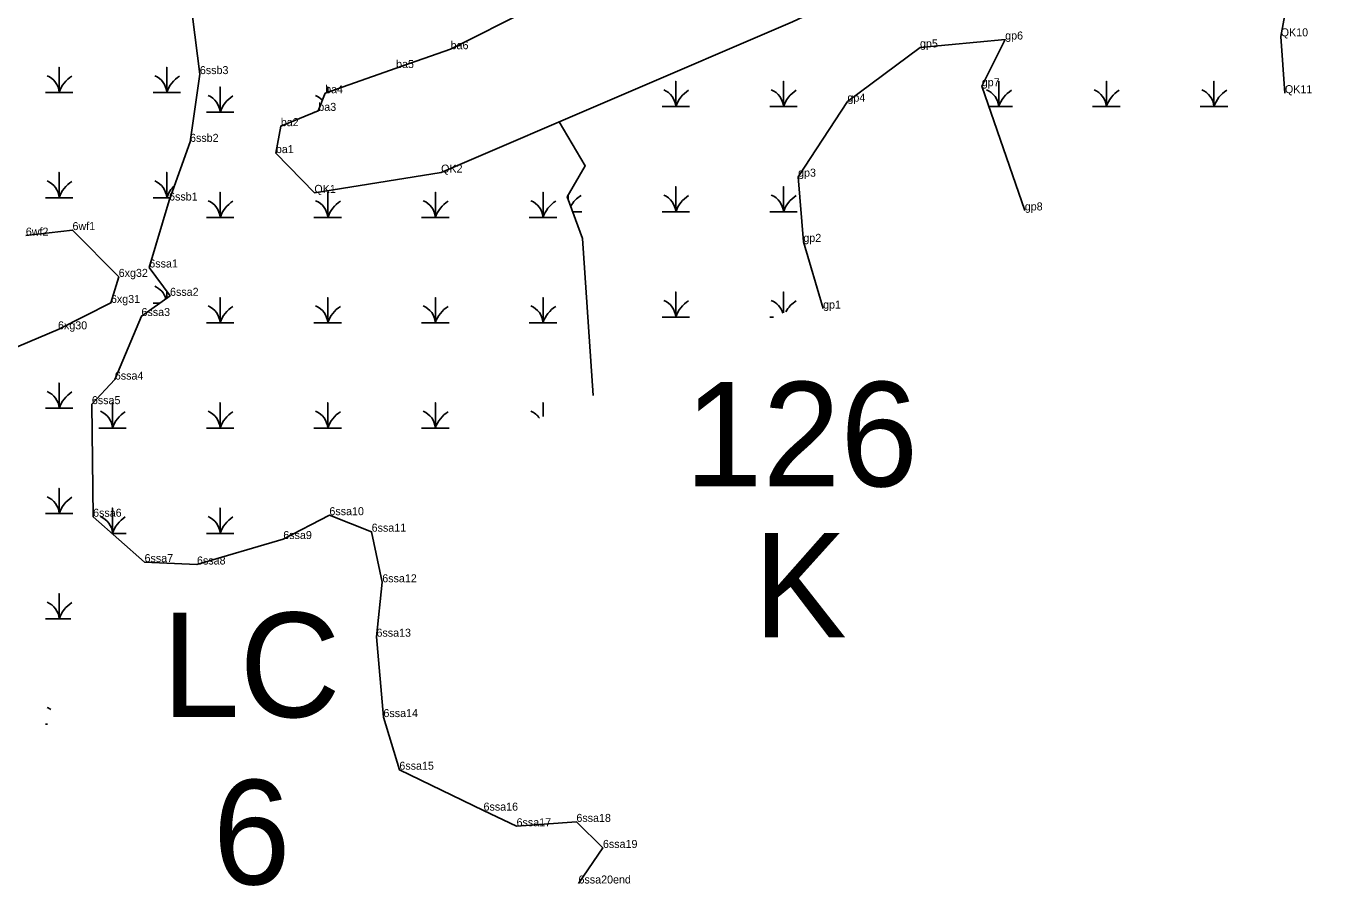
# Model space of a CAD drawing. Extents: x 2072529 to 2268796, y 436423 to 470397.
# Drawn here: x 2153347 to 2154163, y 438196 to 438734 of the extents above; entities that cross this region are included whole.
import ezdxf

# ---------------------------------------------------------------- set-up
doc = ezdxf.new("R2010")
doc.units = 0
for name, color, linetype in [('Default', 7, 'Continuous'), ('Exist Environmental Wetland Boundary', 7, 'Continuous'), ('Exist Environmental Wetland Boundary Cogo Comment', 7, 'Continuous'), ('Exist Environmental Wetland Boundary Cogo Point CELL', 7, 'Continuous'), ('Exist Hydro Jurisdictional Stream or Body of Water NEU Mitigable', 7, 'Continuous'), ('Exist Hydro Jurisdictional Stream or Body of Water NEU Mitigable Cogo Comment', 7, 'Continuous'), ('Exist Hydro Swamp or Marsh', 7, 'Continuous')]:
    doc.layers.add(name, color=color, linetype=linetype)

msp = doc.modelspace()

# ---------------------------------------------------------------- linework, layer by layer
at = {"layer": 'Exist Environmental Wetland Boundary'}
for points in [[(2153527.37, 438629.46), (2153503.31, 438654.33), (2153506.4, 438671.17), (2153529.85, 438680.72), (2153534.13, 438691.75), (2153578.44, 438707.49), (2153612.52, 438719.25), (2153662.11, 438744.35), (2153706.16, 438766.61), (2153742.6, 438780.8), (2153776.72, 438794.85), (2153822.89, 438806.64), (2153857.62, 438820.19), (2153907.12, 438843.71), (2153953.02, 438868.13), (2154021.3, 438890.53), (2154083.94, 438920.93), (2154164.03, 438955.62)], [(2153527.37, 438629.46), (2153606.57, 438642.14), (2153826.22, 438736.39), (2153937.5, 438788.93), (2154046.6, 438844.6), (2154149.14, 438888.4), (2154150.77, 438865.09), (2154136.41, 438848.89), (2154143.66, 438795.63), (2154131.16, 438727.3), (2154133.8, 438691.78)], [(2153845.24, 438557.14), (2153832.91, 438598.85), (2153829.61, 438639.59), (2153860.44, 438686.49), (2153905.78, 438720.37), (2153959, 438725.3), (2153944.36, 438696.13), (2153971.25, 438618.48)], [(2153680.4, 438673.82), (2153696.61, 438646.37), (2153685.41, 438626.93), (2153694.89, 438601), (2153701.53, 438502.86)], [(2153347.1, 438602.75), (2153376.26, 438606.21), (2153405.12, 438576.96), (2153400.27, 438560.67), (2153367.2, 438544.18), (2153242.69, 438491.33)]]:
    msp.add_lwpolyline(points, dxfattribs=at)
at = {"layer": 'Exist Environmental Wetland Boundary Cogo Point CELL'}
for p, q in [((2154131.16, 438727.3), (2154131.16, 438727.3)), ((2153612.52, 438719.25), (2153612.52, 438719.25)), ((2153905.78, 438720.37), (2153905.78, 438720.37)), ((2153959, 438725.3), (2153959, 438725.3)), ((2153455.83, 438703.7), (2153455.83, 438703.7)), ((2153578.44, 438707.49), (2153578.44, 438707.49)), ((2153944.36, 438696.13), (2153944.36, 438696.13)), ((2153534.13, 438691.75), (2153534.13, 438691.75)), ((2153860.44, 438686.49), (2153860.44, 438686.49)), ((2154133.8, 438691.78), (2154133.8, 438691.78)), ((2153529.85, 438680.72), (2153529.85, 438680.72)), ((2153506.4, 438671.17), (2153506.4, 438671.17)), ((2153449.69, 438661.35), (2153449.69, 438661.35)), ((2153503.31, 438654.33), (2153503.31, 438654.33)), ((2153606.57, 438642.14), (2153606.57, 438642.14)), ((2153829.61, 438639.59), (2153829.61, 438639.59)), ((2153527.37, 438629.46), (2153527.37, 438629.46)), ((2153436.6, 438624.69), (2153436.6, 438624.69)), ((2153971.25, 438618.48), (2153971.25, 438618.48)), ((2153376.26, 438606.21), (2153376.26, 438606.21)), ((2153376.26, 438606.21), (2153376.26, 438606.21)), ((2153832.91, 438598.85), (2153832.91, 438598.85)), ((2153424.24, 438582.83), (2153424.24, 438582.83)), ((2153405.12, 438576.96), (2153405.12, 438576.96)), ((2153405.12, 438576.96), (2153405.12, 438576.96)), ((2153437.19, 438565.13), (2153437.19, 438565.13)), ((2153400.27, 438560.67), (2153400.27, 438560.67)), ((2153400.27, 438560.67), (2153400.27, 438560.67)), ((2153845.24, 438557.14), (2153845.24, 438557.14)), ((2153419.35, 438552.51), (2153419.35, 438552.51)), ((2153367.2, 438544.18), (2153367.2, 438544.18)), ((2153367.2, 438544.18), (2153367.2, 438544.18)), ((2153402.71, 438512.76), (2153402.71, 438512.76)), ((2153388.36, 438497.43), (2153388.36, 438497.43)), ((2153389.11, 438427.05), (2153389.11, 438427.05)), ((2153536.77, 438428.03), (2153536.77, 438428.03)), ((2153563.17, 438417.71), (2153563.17, 438417.71)), ((2153507.95, 438413.11), (2153507.95, 438413.11)), ((2153421.28, 438398.69), (2153421.28, 438398.69)), ((2153454.04, 438397.21), (2153454.04, 438397.21)), ((2153569.81, 438386.09), (2153569.81, 438386.09)), ((2153566.18, 438352.08), (2153566.18, 438352.08)), ((2153570.53, 438301.85), (2153570.53, 438301.85)), ((2153580.48, 438268.96), (2153580.48, 438268.96)), ((2153633.07, 438243.38), (2153633.07, 438243.38)), ((2153653.71, 438233.61), (2153653.71, 438233.61)), ((2153691.09, 438236.34), (2153691.09, 438236.34)), ((2153707.68, 438220.06), (2153707.68, 438220.06)), ((2153692.42, 438197.84), (2153692.42, 438197.84))]:
    msp.add_line(p, q, dxfattribs=at)
at = {"layer": 'Exist Hydro Jurisdictional Stream or Body of Water NEU Mitigable'}
for points in [[(2153424.24, 438582.83), (2153436.6, 438624.69), (2153449.69, 438661.35), (2153455.83, 438703.7), (2153451.31, 438739.61), (2153439.32, 438771.61), (2153434.48, 438810.6), (2153429.14, 438886.46), (2153428.13, 438953.78), (2153424.11, 438991.65), (2153418.44, 439064.82)], [(2153692.42, 438197.84), (2153707.68, 438220.06), (2153691.09, 438236.34), (2153653.71, 438233.61), (2153633.07, 438243.38), (2153580.48, 438268.96), (2153570.53, 438301.85), (2153566.18, 438352.08), (2153569.81, 438386.09), (2153563.17, 438417.71), (2153536.77, 438428.03), (2153507.95, 438413.11), (2153454.04, 438397.21), (2153421.28, 438398.69), (2153389.11, 438427.05), (2153388.36, 438497.43), (2153402.71, 438512.76), (2153419.35, 438552.51), (2153437.19, 438565.13), (2153424.24, 438582.83)]]:
    msp.add_lwpolyline(points, dxfattribs=at)
at = {"layer": 'Exist Hydro Swamp or Marsh'}
for points in [[(2153359.31, 438692.23), (2153367.91, 438692.23), (2153367.91, 438708.01), (2153367.91, 438692.23), (2153376.51, 438692.23)], [(2153426.56, 438692.23), (2153435.16, 438692.23), (2153435.16, 438708.01), (2153435.16, 438692.23), (2153443.76, 438692.23)], [(2153459.88, 438679.88), (2153468.48, 438679.88), (2153468.48, 438695.66), (2153468.48, 438679.88), (2153477.08, 438679.88)], [(2153535.73, 438692.32), (2153535.73, 438695.66), (2153535.73, 438692.32)], [(2153744.61, 438683.41), (2153753.21, 438683.41), (2153753.21, 438699.19), (2153753.21, 438683.41), (2153761.81, 438683.41)], [(2153811.86, 438683.41), (2153820.46, 438683.41), (2153820.46, 438699.19), (2153820.46, 438683.41), (2153829.06, 438683.41)], [(2153948.77, 438683.41), (2153954.96, 438683.41), (2153954.96, 438699.19), (2153954.96, 438683.41), (2153963.56, 438683.41)], [(2154013.61, 438683.41), (2154022.21, 438683.41), (2154022.21, 438699.19), (2154022.21, 438683.41), (2154030.81, 438683.41)], [(2154080.86, 438683.41), (2154089.46, 438683.41), (2154089.46, 438699.19), (2154089.46, 438683.41), (2154098.06, 438683.41)], [(2153527.13, 438679.88), (2153527.8, 438679.88)], [(2153359.31, 438626.43), (2153367.91, 438626.43), (2153367.91, 438642.21), (2153367.91, 438626.43), (2153376.51, 438626.43)], [(2153426.56, 438626.43), (2153435.16, 438626.43), (2153435.16, 438642.21), (2153435.16, 438626.43), (2153437.22, 438626.43)], [(2153459.88, 438614.08), (2153468.48, 438614.08), (2153468.48, 438629.86), (2153468.48, 438614.08), (2153477.08, 438614.08)], [(2153527.13, 438614.08), (2153535.73, 438614.08), (2153535.73, 438629.86), (2153535.73, 438614.08), (2153544.33, 438614.08)], [(2153594.38, 438614.08), (2153602.98, 438614.08), (2153602.98, 438629.86), (2153602.98, 438614.08), (2153611.58, 438614.08)], [(2153661.63, 438614.08), (2153670.23, 438614.08), (2153670.23, 438629.86), (2153670.23, 438614.08), (2153678.83, 438614.08)], [(2153744.61, 438617.61), (2153753.21, 438617.61), (2153753.21, 438633.39), (2153753.21, 438617.61), (2153761.81, 438617.61)], [(2153811.86, 438617.61), (2153820.46, 438617.61), (2153820.46, 438633.39), (2153820.46, 438617.61), (2153829.06, 438617.61)], [(2153685.96, 438625.43), (2153685.96, 438627.88)], [(2153685.96, 438627.88), (2153685.96, 438625.43)], [(2153688.82, 438617.61), (2153694.56, 438617.61)], [(2153435.16, 438563.7), (2153435.16, 438567.9)], [(2153435.16, 438567.9), (2153435.16, 438563.7)], [(2153459.88, 438548.28), (2153468.48, 438548.28), (2153468.48, 438564.06), (2153468.48, 438548.28), (2153477.08, 438548.28)], [(2153527.13, 438548.28), (2153535.73, 438548.28), (2153535.73, 438564.06), (2153535.73, 438548.28), (2153544.33, 438548.28)], [(2153594.38, 438548.28), (2153602.98, 438548.28), (2153602.98, 438564.06), (2153602.98, 438548.28), (2153611.58, 438548.28)], [(2153661.63, 438548.28), (2153670.23, 438548.28), (2153670.23, 438564.06), (2153670.23, 438548.28), (2153678.83, 438548.28)], [(2153744.61, 438551.81), (2153753.21, 438551.81), (2153753.21, 438567.59), (2153753.21, 438551.81), (2153761.81, 438551.81)], [(2153820.46, 438554.47), (2153820.46, 438567.59), (2153820.46, 438554.47)], [(2153426.56, 438560.63), (2153430.82, 438560.63)], [(2153811.86, 438551.81), (2153814.34, 438551.81)], [(2153359.31, 438494.83), (2153367.91, 438494.83), (2153367.91, 438510.61), (2153367.91, 438494.83), (2153376.51, 438494.83)], [(2153392.63, 438482.48), (2153401.23, 438482.48), (2153401.23, 438498.26), (2153401.23, 438482.48), (2153409.83, 438482.48)], [(2153459.88, 438482.48), (2153468.48, 438482.48), (2153468.48, 438498.26), (2153468.48, 438482.48), (2153477.08, 438482.48)], [(2153527.13, 438482.48), (2153535.73, 438482.48), (2153535.73, 438498.26), (2153535.73, 438482.48), (2153544.33, 438482.48)], [(2153594.38, 438482.48), (2153602.98, 438482.48), (2153602.98, 438498.26), (2153602.98, 438482.48), (2153611.58, 438482.48)], [(2153670.23, 438489.62), (2153670.23, 438498.26), (2153670.23, 438489.62)], [(2153359.31, 438429.03), (2153367.91, 438429.03), (2153367.91, 438444.81), (2153367.91, 438429.03), (2153376.51, 438429.03)], [(2153400.87, 438416.68), (2153401.23, 438416.68), (2153401.23, 438432.46), (2153401.23, 438416.68), (2153409.83, 438416.68)], [(2153459.88, 438416.68), (2153468.48, 438416.68), (2153468.48, 438432.46), (2153468.48, 438416.68), (2153477.08, 438416.68)], [(2153359.31, 438363.23), (2153367.91, 438363.23), (2153367.91, 438379.01), (2153367.91, 438363.23), (2153375.22, 438363.23)], [(2153359.31, 438297.43), (2153360.73, 438297.43)]]:
    msp.add_lwpolyline(points, dxfattribs=at)
for centre, radius, start, end in [((2153355.65, 438691.34), 12.3, 4.14034, 67.53497), ((2153386.15, 438686.16), 19.22, 122.12745, 161.62219), ((2153422.9, 438691.34), 12.3, 4.14034, 67.53497), ((2153453.4, 438686.16), 19.22, 122.12745, 161.62219), ((2153740.94, 438682.52), 12.3, 4.14034, 67.53497), ((2153771.45, 438677.35), 19.22, 122.12745, 161.62219), ((2153808.19, 438682.52), 12.3, 4.14034, 67.53497), ((2153838.7, 438677.35), 19.22, 122.12745, 161.62219), ((2153942.69, 438682.52), 12.3, 4.14034, 67.53497), ((2153973.2, 438677.35), 19.22, 122.12745, 161.62219), ((2154009.94, 438682.52), 12.3, 4.14034, 67.53497), ((2154040.45, 438677.35), 19.22, 122.12745, 161.62219), ((2154077.19, 438682.52), 12.3, 4.14034, 67.53497), ((2154107.7, 438677.35), 19.22, 122.12745, 161.62219), ((2153456.22, 438679), 12.3, 4.14034, 67.53497), ((2153486.72, 438673.82), 19.22, 122.12745, 161.62219), ((2153523.47, 438679), 12.3, 43.10712, 67.53497), ((2153355.65, 438625.54), 12.3, 4.14034, 67.53497), ((2153386.15, 438620.36), 19.22, 122.12745, 161.62219), ((2153422.9, 438625.54), 12.3, 4.14034, 67.53497), ((2153453.4, 438620.36), 19.22, 134.35762, 161.62219), ((2153740.94, 438616.72), 12.3, 4.14034, 67.53497), ((2153808.19, 438616.72), 12.3, 4.14034, 67.53497), ((2153456.22, 438613.2), 12.3, 4.14034, 67.53497), ((2153486.72, 438608.02), 19.22, 122.12745, 161.62219), ((2153523.47, 438613.2), 12.3, 4.14034, 67.53497), ((2153553.97, 438608.02), 19.22, 122.12745, 161.62219), ((2153590.72, 438613.2), 12.3, 4.14034, 67.53497), ((2153621.22, 438608.02), 19.22, 122.12745, 161.62219), ((2153657.97, 438613.2), 12.3, 4.14034, 67.53497), ((2153688.47, 438608.02), 19.22, 122.12745, 161.62219), ((2153704.2, 438611.55), 19.22, 122.12745, 150.1359), ((2153771.45, 438611.55), 19.22, 122.12745, 161.62219), ((2153838.7, 438611.55), 19.22, 122.12745, 161.62219), ((2153422.9, 438559.74), 12.3, 17.0299, 67.53497), ((2153456.22, 438547.4), 12.3, 4.14034, 67.53497), ((2153486.72, 438542.22), 19.22, 122.12745, 161.62219), ((2153523.47, 438547.4), 12.3, 4.14034, 67.53497), ((2153553.97, 438542.22), 19.22, 122.12745, 161.62219), ((2153590.72, 438547.4), 12.3, 4.14034, 67.53497), ((2153621.22, 438542.22), 19.22, 122.12745, 161.62219), ((2153657.97, 438547.4), 12.3, 4.14034, 67.53497), ((2153688.47, 438542.22), 19.22, 122.12745, 161.62219), ((2153740.94, 438550.92), 12.3, 4.14034, 67.53497), ((2153771.45, 438545.75), 19.22, 122.12745, 161.62219), ((2153808.19, 438550.92), 12.3, 15.83458, 67.53497), ((2153838.7, 438545.75), 19.22, 122.12745, 150.91872), ((2153355.65, 438493.94), 12.3, 4.14034, 67.53497), ((2153386.15, 438488.76), 19.22, 122.12745, 161.62219), ((2153388.97, 438481.6), 12.3, 4.14034, 67.53497), ((2153419.47, 438476.42), 19.22, 122.12745, 161.62219), ((2153456.22, 438481.6), 12.3, 4.14034, 67.53497), ((2153486.72, 438476.42), 19.22, 122.12745, 161.62219), ((2153523.47, 438481.6), 12.3, 4.14034, 67.53497), ((2153553.97, 438476.42), 19.22, 122.12745, 161.62219), ((2153590.72, 438481.6), 12.3, 4.14034, 67.53497), ((2153621.22, 438476.42), 19.22, 122.12745, 161.62219), ((2153657.97, 438481.6), 12.3, 35.17036, 67.53497), ((2153355.65, 438428.14), 12.3, 4.14034, 67.53497), ((2153386.15, 438422.96), 19.22, 122.12745, 161.62219), ((2153388.97, 438415.8), 12.3, 4.14034, 67.53497), ((2153419.47, 438410.62), 19.22, 122.12745, 161.62219), ((2153456.22, 438415.8), 12.3, 4.14034, 67.53497), ((2153486.72, 438410.62), 19.22, 122.12745, 161.62219), ((2153355.65, 438362.34), 12.3, 4.14034, 67.53497), ((2153386.15, 438357.16), 19.22, 122.12745, 161.62219), ((2153355.65, 438296.54), 12.3, 54.72067, 67.53497)]:
    msp.add_arc(centre, radius, start, end, dxfattribs=at)

# ---------------------------------------------------------------- texts
at = {"layer": 'Default'}
for s, p in [('126', (2153758.8, 438446.03)), ('K', (2153801.77, 438351.63)), ('LC', (2153431.99, 438301.82)), ('6', (2153463.92, 438197.27))]:
    msp.add_text(s, height=65.34, dxfattribs=at).set_placement(p)
at = {"layer": 'Exist Environmental Wetland Boundary Cogo Comment'}
for s, p in [('gp6', (2153959, 438725.3)), ('QK10', (2154131.16, 438727.3)), ('ba6', (2153612.52, 438719.25)), ('gp5', (2153905.78, 438720.37)), ('ba5', (2153578.44, 438707.49)), ('ba4', (2153534.13, 438691.75)), ('gp7', (2153944.36, 438696.13)), ('QK11', (2154133.8, 438691.78)), ('ba3', (2153529.85, 438680.72)), ('gp4', (2153860.44, 438686.49)), ('ba2', (2153506.4, 438671.17)), ('ba1', (2153503.31, 438654.33)), ('QK2', (2153606.57, 438642.14)), ('gp3', (2153829.61, 438639.59)), ('QK1', (2153527.37, 438629.46)), ('gp8', (2153971.25, 438618.48)), ('6wf2', (2153347.1, 438602.75)), ('6wf1', (2153376.26, 438606.21)), ('gp2', (2153832.91, 438598.85)), ('6xg32', (2153405.12, 438576.96)), ('6xg31', (2153400.27, 438560.67)), ('gp1', (2153845.24, 438557.14)), ('6xg30', (2153367.2, 438544.18))]:
    msp.add_text(s, height=5, dxfattribs=at).set_placement(p)
at = {"layer": 'Exist Hydro Jurisdictional Stream or Body of Water NEU Mitigable Cogo Comment'}
for s, p in [('6ssb3', (2153455.83, 438703.7)), ('6ssb2', (2153449.69, 438661.35)), ('6ssb1', (2153436.6, 438624.69)), ('6ssa1', (2153424.24, 438582.83)), ('6ssa2', (2153437.19, 438565.13)), ('6ssa3', (2153419.35, 438552.51)), ('6ssa4', (2153402.71, 438512.76)), ('6ssa5', (2153388.36, 438497.43)), ('6ssa10', (2153536.77, 438428.03)), ('6ssa6', (2153389.11, 438427.05)), ('6ssa9', (2153507.95, 438413.11)), ('6ssa11', (2153563.17, 438417.71)), ('6ssa7', (2153421.28, 438398.69)), ('6ssa8', (2153454.04, 438397.21)), ('6ssa12', (2153569.81, 438386.09)), ('6ssa13', (2153566.18, 438352.08)), ('6ssa14', (2153570.53, 438301.85)), ('6ssa15', (2153580.48, 438268.96)), ('6ssa16', (2153633.07, 438243.38)), ('6ssa17', (2153653.71, 438233.61)), ('6ssa18', (2153691.09, 438236.34)), ('6ssa19', (2153707.68, 438220.06)), ('6ssa20end', (2153692.42, 438197.84))]:
    msp.add_text(s, height=5, dxfattribs=at).set_placement(p)

doc.saveas('drawing.dxf')
